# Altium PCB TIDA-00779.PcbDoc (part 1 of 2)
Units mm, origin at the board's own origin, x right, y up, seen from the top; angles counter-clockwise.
Board outline 200 x 145 mm, 2 copper layers (Top Layer, Bottom Layer), stack 1.57 mm thick; 147 components, 60 nets, 299 pads, 545 vias.
Unrouted connection lines stored in the file: 4.
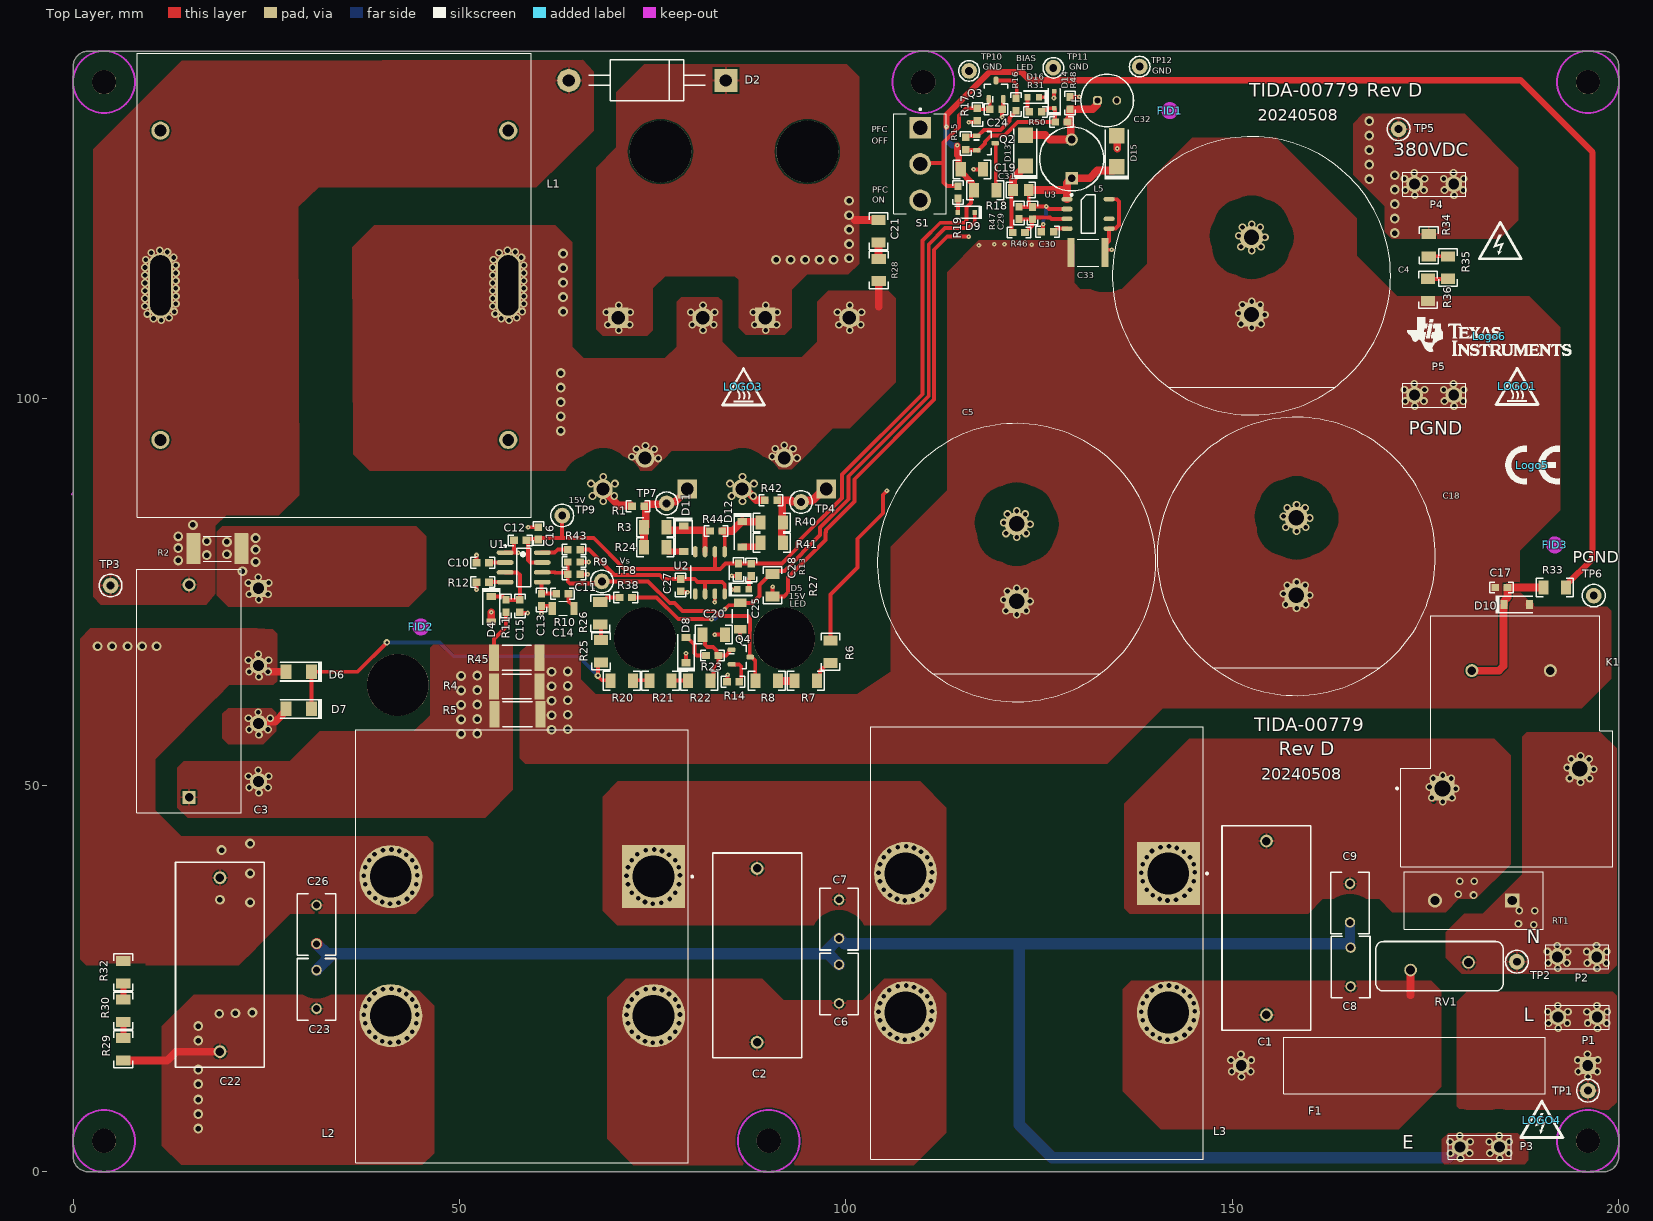
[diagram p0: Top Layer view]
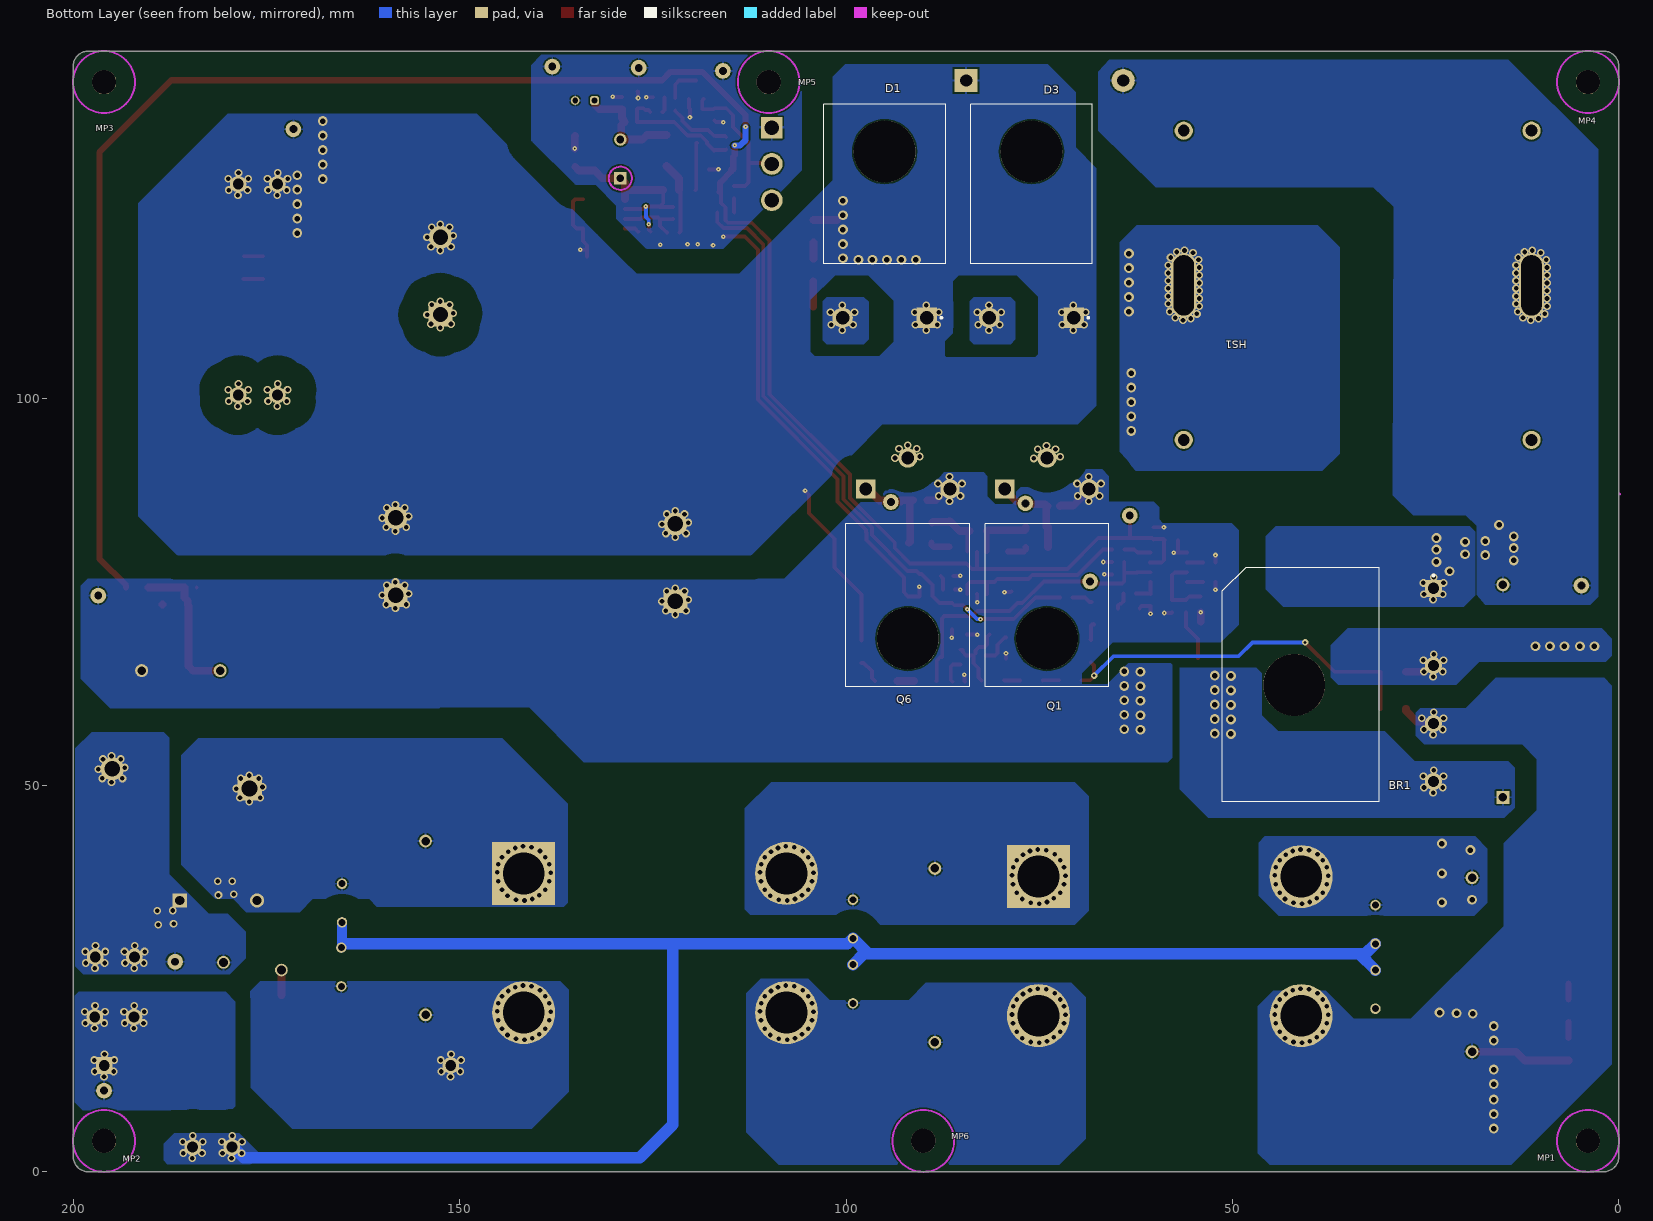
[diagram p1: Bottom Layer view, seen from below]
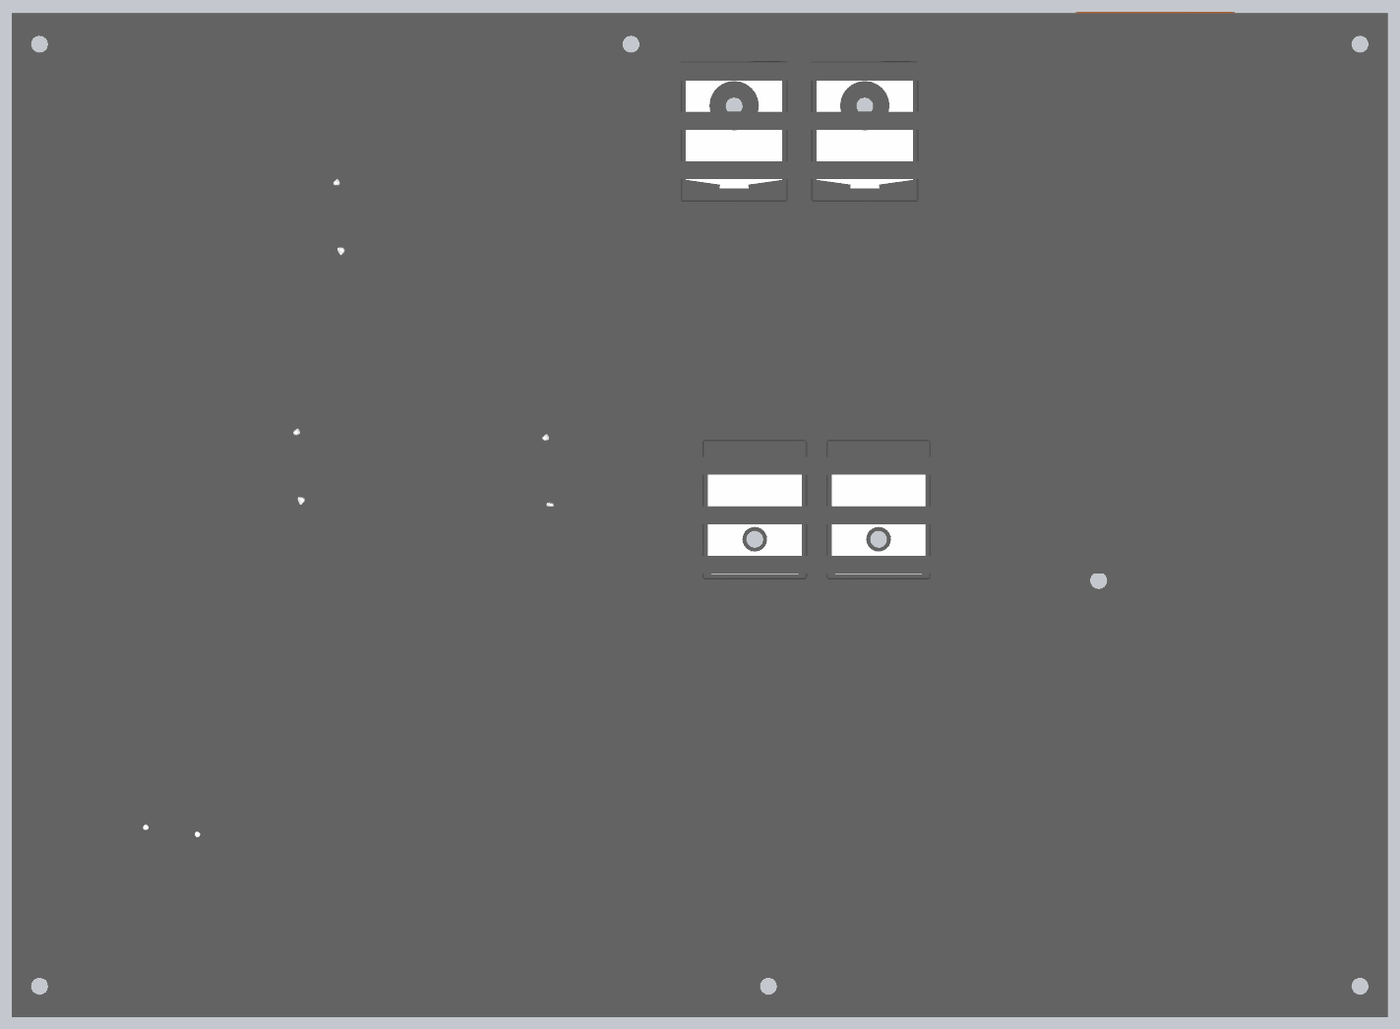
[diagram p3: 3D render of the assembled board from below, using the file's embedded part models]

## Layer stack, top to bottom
Top Solder: solder mask 0.0102, Solder Resist, Dk 3.5
Top Layer: signal copper 0.0356
Dielectric1: core 1.4986, Core-043, Dk 4.3
Bottom Layer: signal copper 0.0356
Bottom Solder: solder mask 0.0102, Solder Resist, Dk 3.5

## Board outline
0,2 0,143 cw(c2,143) 2,145 198,145 cw(c198,143) 200,143 200,2 cw(c198,2) 198,0 2,0 cw(c2,2)

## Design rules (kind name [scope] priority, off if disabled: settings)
AcuteAngle [All] p1: minimum=4.50000000000000E+0001 checktracksonly=FALSE
AssemblyTestPointUsage [All] p1: valid=2
Clearance ACN2EARTH [InNetClass('ACN') vs InNetClass('EARTH')] p1: gap=3 ignorepadtopadclearanceinfootprint=FALSE
Clearance ACN2GND [InNetClass('ACN') vs InNetClass('PGND')] p2: gap=2 ignorepadtopadclearanceinfootprint=FALSE
Clearance ACL2EARTH [InNetClass('ACL') vs InNetClass('EARTH')] p3: gap=3 ignorepadtopadclearanceinfootprint=FALSE
Clearance DCBUS2PGND [InNetClass('DCBUS') vs InNetClass('PGND')] p4: gap=3.2 ignorepadtopadclearanceinfootprint=FALSE
Clearance ACL2ACN [InNetClass('ACL') vs InNetClass('ACN')] p5: gap=2 ignorepadtopadclearanceinfootprint=FALSE
Clearance Clearance_BoardEdge_MountingHoles [OnCopper and InComponentClass('Mounting Holes') vs IsKeepOut] p6: gap=0.3 ignorepadtopadclearanceinfootprint=FALSE except(0: Arc-Hole Track-Hole SMDPad-Hole THPad-Hole Via-Hole Fill-Hole Poly-Hole Region-Hole Text-Hole)
Clearance Clearance_BoardEdge_Poly [OnCopper and InPoly vs IsKeepOut] p7 off: gap=0.25 ignorepadtopadclearanceinfootprint=FALSE except(0: Arc-Hole Track-Hole SMDPad-Hole THPad-Hole Via-Hole Fill-Hole Poly-Hole Region-Hole Text-Hole)
Clearance Clearance_BoardEdge [OnCopper and Not InComponentClass('Logo') and not InComponentClass('FiducialMark') and not InRegion(1000,500,4000,800) and Not IsKeepout vs IsKeepOut] p8 off: gap=1.905 ignorepadtopadclearanceinfootprint=FALSE except(0: Arc-Hole Track-Hole SMDPad-Hole THPad-Hole Via-Hole Fill-Hole Poly-Hole Region-Hole Text-Hole)
Clearance Clearance_Poly [InPolygon] p9: gap=0.2 ignorepadtopadclearanceinfootprint=FALSE
Clearance [All] p10: gap=0.2 ignorepadtopadclearanceinfootprint=FALSE
ComponentClearance ComponentClearance_MountingHoles_FiducialMarks [InComponentClass('Mounting Holes') vs InComponentClass('FiducialMark')] p1 off: gap=1.27 collisioncheckmode=3 verticalgap=0.254 showdistances=FALSE
ComponentClearance ComponentClearance_Shunt [InComponentClass('Header') vs InComponentClass('Shunt')] p2 off: gap=0 collisioncheckmode=3 verticalgap=0 showdistances=FALSE
ComponentClearance ComponentClearance_Logo [InComponentClass('Logo')] p3 off: gap=1.27 collisioncheckmode=3 verticalgap=0.254 showdistances=FALSE
ComponentClearance ComponentClearance_ScrewToNut [(HasFootprint('NY PMS 440 0025 PH')) vs (HasFootprint('Keystone_1902C'))] p4 off: gap=0.127 collisioncheckmode=3 verticalgap=0.254 showdistances=FALSE
ComponentClearance ComponentClearance_MountingHoles [InComponentClass('Mounting Holes')] p5 off: gap=6.35 collisioncheckmode=3 verticalgap=2540 showdistances=FALSE
ComponentClearance ComponentClearance_SmallPassives [HasFootprint('0201*') or HasFootprint('0402*') or HasFootprint('0508') or HasFootprint('0603*') or HasFootprint('0612') or HasFootprint('0805*') or HasFootprint('0815*') or HasFootprint('0830*') or HasFootprint('1206*') or HasFootprint('1210*') or HasFootprint('1808*') or HasFootprint('1812*') or HasFootprint('1825*') or HasFootprint('2010*') or HasFootprint('2220*') or HasFootprint('2225*') or HasFootprint('2512*') or HasFootprint('2728*') or HasFootprint('3518*') vs HasFootprint('0201*') or HasFootprint('0402*') or HasFootprint('0508') or HasFootprint('0603*') or HasFootprint('0612') or HasFootprint('0805*') or HasFootprint('0815*') or HasFootprint('0830*') or HasFootprint('1206*') or HasFootprint('1210*') or HasFootprint('1808*') or HasFootprint('1812*') or HasFootprint('1825*') or HasFootprint('2010*') or HasFootprint('2220*') or HasFootprint('2225*') or HasFootprint('2512*') or HasFootprint('2728*') or HasFootprint('3518*')] p6 off: gap=0.508 collisioncheckmode=3 verticalgap=0.254 showdistances=FALSE
ComponentClearance ComponentClearance_THtoSMT [IsThruComponent vs IsSMTComponent] p7 off: gap=2.54 collisioncheckmode=3 verticalgap=0.762 showdistances=FALSE
ComponentClearance ComponentClearance_THtoTH [IsThruComponent vs IsThruComponent] p8 off: gap=3 collisioncheckmode=3 verticalgap=0.762 showdistances=FALSE
ComponentClearance [All] p9 off: gap=1.016 collisioncheckmode=3 verticalgap=0.254 showdistances=FALSE
DiffPairsRouting [All] p1: maxlimit=2.54 minlimit=0.254 mostfreqgap=0.254 toplayer_minwidth=0.381 toplayer_maxwidth=0.381 toplayer_prefwidth=0.381 bottomlayer_minwidth=0.381 bottomlayer_maxwidth=0.381 bottomlayer_prefwidth=0.381 maxuncoupledlength=25.4
FabricationTestPointUsage TestPointUsage [All] p1: valid=2 allowmultiple=FALSE
FabricationTestpoint Testpoint [All] p1: side=3 testpointundercomponent=TRUE minsize=1.016 maxsize=2.54 preferedsize=1.524 minholesize=0 maxholesize=1.016 preferedholesize=0.813 testpointgrid=0.025 allowsidetop=TRUE allowsidebottom=TRUE usegrid=TRUE gridtolerance=0
FanoutControl Fanout_LCC [IsLCC] p1: bgadir=Out bgaviamode=Centered fanoutstyle=Auto fanoutdirection=Alternating viagrid=0.025 // Fanout_LCC (Default Rule)
FanoutControl Fanout_BGA [IsBGA] p2: bgadir=Out bgaviamode=Centered fanoutstyle=Auto fanoutdirection=Alternating viagrid=0.025 // Fanout_BGA (Default Rule)
FanoutControl Fanout_Default [All] p4: bgadir=Out bgaviamode=Centered fanoutstyle=Auto fanoutdirection=Alternating viagrid=0.025 // Fanout_Default (Default Rule)
FanoutControl Fanout_Small [(CompPinCount < 5)] p5: bgadir=Out bgaviamode=Centered fanoutstyle=Auto fanoutdirection=OutThenIn viagrid=0.025 // Fanout_Small (Default Rule)
HoleSize [All] p1: absolutevalues=TRUE maxlimit=6.375 minlimit=0.2 maxpercent=80.000 minpercent=20.000
MinimumAnnularRing MinimumAnnularRing_ThermalPadVias [IsVia and InAnyComponent] p1: minimumring=0.15
MinimumAnnularRing [All] p2: minimumring=0.2
MinimumSolderMaskSliver MinimumSolderMaskSliver_Logo [InComponentClass('Logo') vs InComponentClass('Logo')] p1: minsoldermaskwidth=0.018
MinimumSolderMaskSliver [All] p2: minsoldermaskwidth=0.1
PlaneClearance [All] p1: clearance=0.2
PlaneConnect [All] p1: planeconnectstyle=Relief reliefexpansion=0.2 reliefentries=4 reliefconductorwidth=0.2 reliefairgap=0.2
PolygonConnect PolygonDirect [InComponent('L2') or InComponent('L3') or InComponent('K1') or InComponent('L1') or InComponent('D1') or InComponent('D3') or InComponent('C4') or InComponent('C5') or InComponent('C18') or InComponent('F1')  or InComponent('RT1') or InComponent('P1') or InComponent('P2') or InComponent('P3') or InComponent('BR1') or InComponent('Q1')  or InComponent('Q6') or InComponent('R4') or InComponent('R5') or InComponent('R45')or InComponent('R2')or InComponent('P4') or InComponent('P5')] p1: connectstyle=Direct reliefconductorwidth=0.2 reliefentries=4 polygonreliefangle="90 Angle" airgapwidth=0.2
PolygonConnect [All] p2: thpad.connectstyle=Relief thpad.reliefconductorwidth=0.3 thpad.reliefentries=4 thpad.polygonreliefangle="90 Angle" thpad.airgapwidth=0.2 smdpad.connectstyle=Direct smdpad.reliefconductorwidth=0.3 smdpad.reliefentries=4 smdpad.polygonreliefangle="90 Angle" smdpad.airgapwidth=0.2 via.connectstyle=Direct via.reliefconductorwidth=0.2 via.reliefentries=4 via.polygonreliefangle="90 Angle" via.airgapwidth=0.2
RoutingVias ThermalPadVias [IsVia and InAnyComponent] p1: holewidth=0.2 width=0.5 viastyle="Through Hole" minholewidth=0.2 minwidth=0.5 maxholewidth=0.33 maxwidth=0.6
RoutingVias [All] p2: holewidth=0.2 width=0.6 viastyle="Through Hole" minholewidth=0.2 minwidth=0.6 maxholewidth=1 maxwidth=4
SilkToSilkClearance SilkToSilkClearance_Pb-FreeLogo [(HasFootprint('Pb-Free_Overlay_Medium') OR HasFootprint('Pb-Free_Overlay_Small')) vs (HasFootprint('Pb-Free_Overlay_Medium') OR HasFootprint('Pb-Free_Overlay_Small'))] p1: silktosilkclearance=0
SilkToSilkClearance [All] p2: silktosilkclearance=0.102
SilkToSolderMaskClearance "Silk to Solder Mask Opening" [IsPad] p1: minsilkscreentomaskgap=0.102 clearancetoexposedcopper=TRUE
SolderMaskExpansion [All] p1: expansion=0.05 istentingtop=FALSE
Width [All] p1: maxlimit=10 minlimit=0.2 preferedwidth=0.254 minimp=50.000000 maximp=50.000000 favimp=50.000000 checkconnectedcopper=TRUE
15 further rules are at their usual default settings.

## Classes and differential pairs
component class Logo: Logo6
net class EARTH: GNDE
net class DCBUS: NetBR1_1 NetC3_2 NetC21_2 NetD1_2 NetR34_1 VDCBUS
net class ACL: NetBR1_3 NetC1_2 NetC2_2 NetF1_1 NetR29_1 NetR30_1
net class ACN: NetBR1_2 NetBR1_3 NetC1_2 NetC2_1 NetC2_2 RLY-N RLY-P
net class PGND: 15V ACSENSE BIAS InrushDelay NetC10_1 NetC13_1 NetC14_2 NetC15_1 NetC17_1 NetC24_1 NetC27_1 NetC32_1 NetD5_1 NetD8_2 NetD9_2 NetD11_1 NetD11_2 NetD12_1 NetD12_2 NetD16_1 NetL1_1 NetL1_2 NetL1_3 NetL1_4 NetQ1_1 NetQ2_1 NetQ2_3 NetQ3_3 NetQ4_2 NetQ6_1 NetR6_1 NetR7_1 NetR12_2 NetR21_1 NetR26_1 NetR35_1 NetR43_1 NetS1_1 NetU2_1 NetU2_8 PGND RTN Vsense
component class FiducialMark: FID1 FID2 FID3

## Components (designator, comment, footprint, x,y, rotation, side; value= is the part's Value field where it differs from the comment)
BR1 "GBJ3510" FP-GBJ3510_HOR_GBJ3510_HOR-MFG 41.15,63 r90 bottom locked
C1 "890334026027CS" WCAP-FTXX_L26W11H20_CS 154.4,31.55 r270 top
C2 "890334026027CS" WCAP-FTXX_L26W11H20_CS 88.5,28 r270 top
C3 "890334027012CS" FP-890334027012CS_RADIAL-MFG 15,62.2 r90 top value=1.2µF
C4 "861141486026" FP-861141486026_RADIAL-MFG 152.464,115.923 r90 top locked value=680µF
C5 "861141486026" FP-861141486026_RADIAL-MFG 122.064,78.823 r90 top value=680µF
C6 "DE2E3KY222MA2BM01F" KY_800x500x1100 99.1,24.3 r270 top value=2200pF
C7 "DE2E3KY222MA2BM01F" KY_800x500x1100 99.1,32.7 r90 top value=2200pF
C8 "DE2E3KY222MA2BM01F" KY_800x500x1100 165.3,26.5 r270 top value=2200pF
C9 "DE2E3KY222MA2BM01F" KY_800x500x1100 165.207,34.774 r90 top value=2200pF
C10 "GRM188R72A332KA01D" 0603 53,78.8 r180 top value=3300pF
C11 "GRM188R71H821KA01D" 0603 64.8,77.3 r0 top value=820pF
C12 "GRT188R61H105ME13D" 0603 57.85,81.7 r180 top value=1uF
C13 "GRM188R71C394KA88D" 0603 60.6,74 r270 top value=0.39uF
C14 "C1206C825M8RAC7800" FP-C1206C825M8RAC7800_1206-MFG 63.4,72.9 r0 top value=8.2µF
C15 "GRM1885C1H272JA01D" 0603 57.8,73.2 r270 top value=2700pF
C16 "GCM188R71H104KA57D" 0603 60.2,82.6 r90 top value=0.1uF
C17 "GRT188R61H105ME13D" 0603 184.8,75.6 r180 top value=1uF
C18 "861141486026" FP-861141486026_RADIAL-MFG 158.264,79.623 r90 top locked value=680µF
C19 "GRM319R6YA106KA12D" 1206 116.3,129.7 r0 top value=10uF
C20 "GRM319R6YA106KA12D" 1206 82.9,69.5 r0 top value=10uF
C21 "GRM31A7U3A221JW31D" 1206 104.2,121.7 r270 top value=220pF
C22 "890334026027CS" WCAP-FTXX_L26W11H20_CS 19,26.8 r270 top
C23 "DE2E3KY222MA2BM01F" KY_800x500x1100 31.5,23.6 r270 top value=2200pF
C24 "GCM188R71H104KA57D" 0603 119.4,137.475 r0 top value=0.1uF
C25 "C3216X5R1V226M160AC" 1206_180 86.3,71.9 r270 top value=22uF
C26 "DE2E3KY222MA2BM01F" KY_800x500x1100 31.5,32 r90 top value=2200pF
C27 "GRM1885C1H221JA01D" 0603 78.6,75.9 r270 top value=220pF
C28 "GRT188R61H105ME13D" 0603 86.1,77.9 r90 top value=1uF
C29 "GRM1885C1H200JA01D" 0603 124.123,124.036 r90 top value=20pF
C30 "GCM188R71H104KA57D" 0603 126.064,121.623 r180 top value=0.1uF
C31 "GRM219R71H334KA88D" 0805_HV 122.623,127.036 r0 top value=0.33uF
C32 "35ZLJ100M6.3X11" Rubycon_630x1100 133.79,138.609 r0 top value=100uF
C33 "885342211006" FP-885342211006_1812-MFG 131.323,118.936 r0 top value=100nF
D1 "BYC30W-600PQ" FP-BYC30W-600PQ_HOR_TO-247-2-MFG 95,127.8 r180 bottom locked
D2 "1N5406" DO-201AD 74.3,141.2 r180 top value=600V
D3 "BYC30W-600PQ" FP-BYC30W-600PQ_HOR_TO-247-2-MFG 76,127.8 r180 bottom locked
D4 "BAT54T1G" SOD-123 54.1,72.8 r270 top value=30V
D5 "LTST-C193KGKT-5A" LTST-C193_Green 86.677,75.364 r180 top value=Green
D6 "CGRM4007-G" MINI-SMA 29.2,64.7 r180 top value=1000V
D7 "CGRM4007-G" MINI-SMA 29.2,59.9 r180 top value=1000V
D8 "BAT54T1G" SOD-123 79.3,67.5 r90 top value=30V
D9 "MMSZ5248BS-7-F" SOD-323 115.567,124.125 r180 top value=18V
D10 "BAT54T1G" SOD-123 186.8,73.4 r0 top value=30V
D11 "1N4148W-7-F" SOD-123 79,81.9 r270 top value=100V
D12 "1N4148W-7-F" SOD-123 86.6,82.5 r270 top value=100V
D13 "US1M-13-F" SMA 123.223,132.136 r90 top value=1000V
D14 "MMSZ5248BS-7-F" SOD-323 126.959,138.7 r90 top value=18V
D15 "US1M-13-F" SMA 135.023,132.036 r90 top value=1000V
D16 "LTST-C193KRKT-5A" LTST-C193_Red 124.223,139.036 r0 top value=Red
F1 "0525025.MXEP" FP-0525025.MXEP_AXIAL-MFG 173.551,13.758 r180 top
FID1 "Fiducial" Fiducial10-20 141.9,137.3 r0 top
FID2 "Fiducial" Fiducial10-20 45,70.5 r0 top
FID3 "Fiducial" Fiducial10-20 191.7,81.1 r0 top
HS1 "TIDA-00779 Heatsink" 0-MFG 100,72.5 r270 bottom
K1 "T9AS1D12-12" FP-T9AS1D12-12_PTH_RELAY_27MM43_32MM51-MFG 185.499,55.7 r180 top
L1 "30A_170uH" FP-30A_170uH_PTH_IND_60MM0_51MM0-MFG 33.8,114.7 r90 top value=170uH
L2 "30A_2.5mH" FP-30A_2.5mH_PTH_CMC_56MM0_42MM0-MFG 58.1,29.2 r270 top
L3 "30A_2.5mH" FP-30A_2.5mH_PTH_CMC_56MM0_42MM0-MFG 124.7,29.6 r270 top
L5 "768772182" WE-TI_8095 129.197,131.05 r90 top value=1.8mH
LOGO1 "CAUTION HOT SURFACE" IEC_HotSurface_Small 186.823,101.636 r0 top
LOGO3 "CAUTION HOT SURFACE" IEC_HotSurface_Small 86.736,101.577 r0 top
LOGO4 "DANGER HIGH VOLTAGE" IEC_HighVoltage_Small 190.036,6.677 r0 top
Logo5 "CE Mark" CE_Mark_5mm 188.823,91.436 r0 top
Logo6 "Texas Instruments" TI_Stacked_Overlay_Small 183.236,108.077 r0 top
MP1 "970130365" FP-970130365_SPCAER_M3-MFG 4,4 r180 bottom
MP2 "970130365" FP-970130365_SPCAER_M3-MFG 196,4 r180 bottom
MP3 "970130365" FP-970130365_SPCAER_M3-MFG 196,141 r180 bottom
MP4 "970130365" FP-970130365_SPCAER_M3-MFG 4,141 r180 bottom
MP5 "970130365" FP-970130365_SPCAER_M3-MFG 110,141 r180 bottom
MP6 "970130365" FP-970130365_SPCAER_M3-MFG 90,4 r180 bottom
P1 "63824-1" FP-63824-1_CONN_7MM92_3MM11-MFG 194.651,20.025 r0 top
P2 "63824-1" FP-63824-1_CONN_7MM92_3MM11-MFG 194.6,27.8 r180 top
P3 "63824-1" FP-63824-1_CONN_7MM92_3MM11-MFG 182,3.2 r0 top
P4 "63824-1" FP-63824-1_CONN_7MM92_3MM11-MFG 176.1,127.8 r0 top
P5 "63824-1" FP-63824-1_CONN_7MM92_3MM11-MFG 176.1,100.5 r0 top
Q1 "IPW60R099CPFKSA1" FP-IPW60R099CPFKSA1_HOR_TO247-MFG 74,73.305 r180 bottom locked
Q2 "MMBT3906-7-F" SOT-23 118.1,133.1 r0 top value="40 V"
Q3 "2V7002KT1G" SOT-23 119.4,140 r90 top value=60V
Q4 "MMBT3904-7-F" SOT-23 86.4,66.6 r0 top value="40 V"
Q6 "IPW60R099CPFKSA1" FP-IPW60R099CPFKSA1_HOR_TO247-MFG 92,73.305 r180 bottom locked
R1 "RC0603FR-0710KL" 0603 73.1,86.1 r0 top value=10.0k
R2 "RC2512FK-070RL" FP-RC2512FK-070RL_2512-MFG 18.664,80.623 r180 top value=0
R3 "RC1206FR-0722RL" 1206 75.3,83.4 r180 top value=22.0
R4 "ERJ-M1WSF10MU" 2512 57.4,62.8 r180 top value=0.01
R5 "ERJ-M1WSF10MU" 2512 57.5,59.2 r180 top value=0.01
R6 "RC1206FR-07332KL" 1206 98,67.3 r90 top value=332k
R7 "RC1206FR-07332KL" 1206 94.8,63.525 r0 top value=332k
R8 "RC1206FR-07332KL" 1206 89.75,63.525 r0 top value=332k
R9 "RC0603FR-0718KL" 0603 64.8,78.9 r180 top value=18.0k
R10 "RC0603FR-0710KL" 0603 63.3,74.8 r180 top value=10.0k
R11 "RC0603FR-07220RL" 0603 56,73.2 r270 top value=220
R12 "RC0603FR-0747KL" 0603 53,76.3 r0 top value=47.0k
R13 "RC0603FR-0710KL" 0603 87.736,77.877 r270 top value=10.0k
R14 "RC0603FR-0716K2L" 0603 85.4,63.4 r0 top value=16.2k
R15 "RC0603FR-0710KL" 0603 115.5,133.05 r90 top value=10.0k
R16 "RC0603FR-071KL" 0603 122,138.1 r90 top value=1.00k
R17 "RC0603FR-0747KL" 0603 117,136.8 r90 top value=47.0k
R18 "RC1206FR-071RL" 1206 118,127 r180 top value=1.00
R19 "RC0603FR-0710KL" 0603 114.5,126.725 r270 top value=10.0k
R20 "RC1206FR-07332KL" 1206 71,63.544 r180 top value=332k
R21 "RC1206FR-07332KL" 1206 76.002,63.544 r180 top value=332k
R22 "RC1206FR-07332KL" 1206 81,63.544 r180 top value=332k
R23 "RC0603FR-0710KL" 0603 82.7,66.8 r0 top value=10.0k
R24 "RC1206FR-074R7L" 1206 75.3,80.8 r180 top value=4.70
R25 "RC1206FR-07332KL" 1206 68.3,67.35 r270 top value=332k
R26 "RC1206FR-07332KL" 1206 68.2,72.25 r270 top value=332k
R27 "RC1206FR-07332KL" 1206 90.5,75.9 r90 top value=332k
R28 "RC1206FR-0722RL" 1206 104.236,116.677 r270 top value=22.0
R29 "RC1206FR-07100KL" 1206 6.5,15.85 r270 top value=100k
R30 "RC1206FR-07100KL" 1206 6.5,20.85 r270 top value=100k
R31 "RC0603FR-0710KL" 0603 124.523,137.136 r0 top value=10.0k
R32 "RC1206FR-07100KL" 1206 6.5,25.8 r270 top value=100k
R33 "RC1206FR-0722RL" 1206 191.7,75.6 r180 top value=22.0
R34 "RC1206FR-07100KL" 1206 175.4,119.9 r90 top value=100k
R35 "RC1206FR-07100KL" 1206 177.9,117 r90 top value=100k
R36 "RC1206FR-07100KL" 1206 175.3,114.1 r90 top value=100k
R38 "RC0603FR-0747KL" 0603 71.5,74.3 r180 top value=47.0k
R40 "RC1206FR-0722RL" 1206 90.4,84 r0 top value=22.0
R41 "RC1206FR-074R7L" 1206 90.4,81.4 r0 top value=4.70
R42 "RC0603FR-0710KL" 0603 90.3,86.9 r0 top value=10.0k
R43 "RT0603DRE07100RL" 0603 64.8,80.5 r0 top value=100
R44 "RC0603JR-070RL" 0603 83.2,82.9 r0 top value=0
R45 "ERJ-M1WSF10MU" 2512 57.4,66.5 r180 top value=0.01
R46 "RC0603FR-07133KL" 0603 122.364,121.523 r180 top value=133k
R47 "RC0603FR-0710KL" 0603 122.377,124.064 r270 top value=10.0k
R48 "RC0603FR-0721KL" 0603 128.977,138.264 r270 top value=21.0k
R50 "RC0603JR-070RL" 0603 127.864,135.823 r180 top value=0
RT1 "PPL16500NA2B7Y" FP-PPL16500NA2B7Y_RADIAL-MFG 181.2,35.1 r180 top value=50Ω
RV1 "MOV-14D471K" Bourns_MOV-14D621K 176.8,26.6 r180 top
S1 "472123010111" FP-472123010111_PTH3-MFG 109.6,130.4 r90 top
TP1 "5000" Keystone5000 196,10.5 r0 top value=Red
TP2 "5000" Keystone5000 186.8,27.187 r0 top value=Red
TP3 "5000" Keystone5000 4.85,75.85 r0 top value=Red
TP4 "5000" Keystone5000 94.187,86.662 r0 top value=Red
TP5 "5000" Keystone5000 171.5,134.9 r0 top value=Red
TP6 "5001" Keystone5001 196.75,74.55 r0 top value=Black
TP7 "5000" Keystone5000 76.783,86.485 r0 top value=Red
TP8 "5000" Keystone5000 68.417,76.385 r0 top value=Red
TP9 "5000" Keystone5000 63.281,84.906 r0 top value=Red
TP10 "5001" Keystone5001 115.923,142.436 r90 top
TP11 "5001" Keystone5001 126.823,142.836 r90 top
TP12 "5001" Keystone5001 138,143 r90 top
U1 "UCC28180D" D0008A_N#1 58.3,78.2 r0 top
U2 "UCC27524DR" D0008A_N#2 82.4,77.5 r90 top
U3 "UCC28881DR" D0007A_N 131.323,123.936 r0 top
? "DANGER HIGH VOLTAGE" IEC_HighVoltage_Small 184.636,120.377 r0 top

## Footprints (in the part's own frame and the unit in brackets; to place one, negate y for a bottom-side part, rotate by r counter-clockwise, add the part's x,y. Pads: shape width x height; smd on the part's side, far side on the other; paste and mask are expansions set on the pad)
0-MFG [mm]
  body extent -73,-100 73,100, height 22
0603 [mm] "0603 from SM-752 data"
  rect 1x0.95 smd: 1(-0.8,0) 2(0.8,0)
  silkscreen extent -1.52,-0.69 1.52,0.69, body extent -0.87,-0.47 0.87,0.47, height 1
0805_HV [mil] "0805 with 30mil clearance between pads"
  rect 50x63 smd: 1(-40,0) 2(40,0)
  silkscreen extent -74,-40 74,40, body extent -43,-29 43,29, height 57
1206 [mm] "1206 from SM-752 data"
  rect 1.3x1.85 smd: 1(-1.45,0) 2(1.45,0)
  silkscreen extent -2.4,-1.21 2.4,1.21, body extent -1.7,-0.9 1.7,0.9, height 1.35
1206_180 [mm] "1206_180"
  rect 1.1x1.6 smd: 1(-1.7,0) 2(1.7,0)
  silkscreen extent -0.9,-1 0.9,1, body extent -1.75,-0.95 1.75,0.95, height 1.8
2512 [mm] "Chip Resistor, Body 6.3x3.2mm, IPC Medium Density"
  rect 1.3x3.4 smd: 1(-2.95,0) 2(2.95,0)
  silkscreen extent -1.9,-1.6 1.9,1.6, body extent -3.22,-1.67 3.22,1.67, height 0.71
Bourns_MOV-14D621K [mm] "TH, 2-Leads, Dia 16.5mm"
  round 1.65 hole 1.15: 1(-3.75,-0.5) 2(3.75,0.5)
  silkscreen extent -8.25,-3.2 8.25,3.2, body extent -8.25,-3.2 8.25,3.2, height 21.97
CE_Mark_5mm [mm] "Minimum text height for CE Mark"
  silkscreen extent -3.5,-2.5 3.5,2.5
D0007A_N [mm] "SOIC, 7-Leads, Body 4.9x3.9mm, Pitch 1.27mm, IPC Medium Density"
  oval 1.45x0.6 smd: 1(-2.725,1.905) 2(-2.725,0.635) 3(-2.725,-0.635) 4(-2.725,-1.905) 5(2.725,-1.905) 6(2.725,-0.635) 8(2.725,1.905)
  silkscreen extent -0.9,-2.5 0.9,2.5, body extent -3.01,-2.45 3.01,2.45, height 1.75
D0008A_N#1 [mm] "SOIC, 8-Leads, Body 4.9x3.9mm, Pitch 1.27mm, IPC Medium Density"
  oval 2.2x0.6 smd: 1(-2.4,1.905) 2(-2.4,0.635) 3(-2.4,-0.635) 4(-2.4,-1.905) 5(2.4,-1.905) 6(2.4,-0.635) 7(2.4,0.635) 8(2.4,1.905)
  silkscreen extent -2.52,-2.5 0.9,2.88, body extent -2,-2.5 2,2.5, height 1.75
D0008A_N#2 [mm] "SOIC, 8-Leads, Body 4.9x3.9mm, Pitch 1.27mm, IPC Medium Density"
  oval 1.45x0.6 smd: 1(-2.725,1.905) 2(-2.725,0.635) 3(-2.725,-0.635) 4(-2.725,-1.905) 5(2.725,-1.905) 6(2.725,-0.635) 7(2.725,0.635) 8(2.725,1.905)
  silkscreen extent -3.3,-2.5 0.9,2.5, body extent -3,-2.45 3,2.45, height 1.63
DO-201AD [mm] "Vishay dimensions"
  rect 3x3 hole 1.6: 1(-10.16,0)
  round 3 hole 1.6: 2(10.16,0)
  silkscreen extent -7.47,-2.7 7.57,2.61, body extent -10.82,-2.74 10.82,2.61, height 5.33
Fiducial10-20 [mm]
  round 1 smd mask+0.5: 1(0,0)
  Top Layer keep-out circle w1.178: c0,0 r0.5
FP-30A_2.5mH_PTH_CMC_56MM0_42MM0-MFG [mm]
  rrect1% 8.15x8.15 hole 5.4 paste-2539.97 mask+0: 1(-9,17)
  round 8.15 hole 5.4 paste-2539.97 mask+0: 2(-9,-17) 3(9,-17) 4(9,17)
  silkscreen extent -28,-21.5 28,22.13, body extent -28.1,-21.6 28.1,21.6, height 0.25
FP-30A_170uH_PTH_IND_60MM0_51MM0-MFG [mm]
  round 2.35 hole 1.55 paste-2539.97 mask+0: 1(-20,22.5) 2(20,22.5) 3(-20,-22.5) 4(20,-22.5)
  rrect100% 8.4x3.25 hole 2.65 slot 7.8 at 0 deg paste-2539.97 mask+0: N(0,-22.5) S(0,22.5)
  silkscreen extent -30,-25.5 30,25.5, body extent -30.1,-25.6 30.1,25.6, height 0.25
FP-63824-1_CONN_7MM92_3MM11-MFG [mm]
  round 2.15 hole 1.4 paste-2539.97 mask+0: 1(-2.54,0) 1(2.54,0)
  silkscreen extent -4.09,-1.56 4.09,1.56, body extent -3.96,-1.54 3.96,1.54, height 10.88
FP-0525025.MXEP_AXIAL-MFG [mm]
  rrect5% 2.15x2.15 hole 1.4 paste-2539.97 mask+0: 1(-22.42,0)
  round 2.15 hole 1.4 paste-2539.97 mask+0: 2(22.42,0)
  silkscreen extent -16.92,-3.64 16.92,3.64, body extent -23.59,-3.74 23.59,3.74, height 0.25
FP-970130365_SPCAER_M3-MFG [mm]
  round 3.15 hole 3.15 unplated paste-2539.97 mask+0: ""(0,0)
  body extent -3.46,-3 3.46,3, height 13.1
FP-472123010111_PTH3-MFG [mm]
  rrect4% 2.8x2.8 hole 1.85 paste-2539.97 mask+0: 1(4.7,0)
  round 2.8 hole 1.85 paste-2539.97 mask+0: 2(0,0) 3(-4.7,0)
  silkscreen extent -6.48,-3.4 7.2,3.4, body extent -6.58,-3.5 6.58,3.5, height 0.25
FP-861141486026_RADIAL-MFG [mm]
  rrect3% 3.05x3.05 hole 2 paste-2539.97 mask+0: 1(-5,0)
  round 3.05 hole 2 paste-2539.97 mask+0: 2(5,0)
  silkscreen extent -18,-18 18,18, body extent -18.1,-18.1 18.1,18.1, height 0.25
FP-885342211006_1812-MFG [mm]
  rrect11% 0.9x3.8 smd paste+0 mask+0: 1(-2.2,0) 2(2.2,0)
  silkscreen extent -1.38,-1.75 1.38,1.75, body extent -2.75,-2 2.75,2, height 0.25
FP-890334027012CS_RADIAL-MFG [mm]
  rrect6% 1.7x1.7 hole 1.1 paste-2539.97 mask+0: 1(-13.75,0)
  round 1.7 hole 1.1 paste-2539.97 mask+0: 2(13.75,0)
  silkscreen extent -15.75,-6.75 15.75,6.75, body extent -15.85,-6.85 15.85,6.85, height 0.25
FP-BYC30W-600PQ_HOR_TO-247-2-MFG [mm]
  rrect4% 2.65x2.65 hole 1.75 paste-2539.97 mask+0: 1(5.45,-17.3)
  round 2.65 hole 1.75 paste-2539.97 mask+0: 2(-5.45,-17.3)
  round 8 hole 8 unplated paste-2539.97 mask+0: ""(0,4.2)
  silkscreen extent -7.88,-17.42 7.88,10.3, body extent -7.8,-17.55 7.8,10.73, height 5.2
FP-C1206C825M8RAC7800_1206-MFG [mm]
  rrect11% 0.95x1.7 smd paste+0 mask+0: 1(-1.4,0) 2(1.4,0)
  silkscreen extent -0.55,-0.9 0.55,0.9, body extent -2,-1 2,1, height 0.25
FP-GBJ3510_HOR_GBJ3510_HOR-MFG [mm]
  rrect5% 2.2x2.2 hole 1.45 paste-2539.97 mask+0: 1(12.5,-17.15)
  round 2.2 hole 1.45 paste-2539.97 mask+0: 2(2.5,-17.15) 3(-5,-17.15) 4(-12.5,-17.15)
  round 8 hole 8 unplated paste-2539.97 mask+0: ""(0,0.85)
  silkscreen extent -15.15,-17.27 15.15,10.15, body extent -15,-17.45 15,10.15, height 4.8
FP-IPW60R099CPFKSA1_HOR_TO247-MFG [mm]
  rrect4% 2.5x2.5 hole 1.65 paste-2539.97 mask+0: 1(-5.45,15.038)
  round 2.5 hole 1.65 paste-2539.97 mask+0: 2(0,19.038) 3(5.45,15.038)
  round 8 hole 8 unplated paste-2539.97 mask+0: ""(0,-4.305)
  silkscreen extent -8.01,-10.54 8.01,10.54, body extent -7.93,-10.47 7.93,19.41, height 5.16
FP-PPL16500NA2B7Y_RADIAL-MFG [mm]
  rrect5% 1.85x1.85 hole 1.2 paste-1000 mask+0: 1(-5,0)
  round 1.85 hole 1.2 paste-1000 mask+0: 2(5,0)
  silkscreen extent -9,-3.75 9,3.75, body extent -9.1,-3.85 9.1,3.85, height 0.25
FP-RC2512FK-070RL_2512-MFG [mm]
  rrect6% 1.8x4 smd paste+0 mask+0: 1(-3.1,0) 2(3.1,0)
  silkscreen extent -1.83,-1.63 1.83,1.63, body extent -4.1,-2.1 4.1,2.1, height 0.25
FP-T9AS1D12-12_PTH_RELAY_27MM43_32MM51-MFG [mm]
  rrect3% 3.16x3.16 hole 2.06 paste-2539.97 mask+0: 1(8.335,6.095)
  round 3.03 hole 1.98 paste-2539.97 mask+0: 2(-9.445,3.555)
  round 1.69 hole 1.09 paste-2539.97 mask+0: 3(4.525,-9.145) 4(-5.635,-9.145)
  silkscreen extent -13.71,-16.25 14.31,16.25, body extent -13.81,-16.35 13.81,16.35, height 0.25
IEC_HighVoltage_Small [mm]
  silkscreen extent -2.72,-2.24 2.72,2.47
IEC_HotSurface_Small [mm]
  silkscreen extent -2.72,-2.36 2.72,2.35
Keystone5000 [mil] "For Keystone 500x miniature loop terminals"
  round 80 hole 40: 1(0,0)
  silkscreen extent -58,-58 58,58, body extent -49,-49 49,49, height 182
Keystone5001 [mil] "For Keystone 500x miniature loop terminals"
  round 80 hole 40: 1(0,0)
  silkscreen extent -58,-58 58,58, body extent -49,-49 49,49, height 182
KY_800x500x1100 [mm] "TH, 2- Leads, Body 8x5mm, Pin Spacing 5mm"
  round 1.35 hole 0.9: 1(-2.5,0) 2(2.5,0)
  silkscreen extent -4,-2.5 4,2.5, body extent -4,-2.5 4,2.5, height 12
LTST-C193_Green [mm] "SMD, 2-Leads, Body1.6x0.8mm"
  rect 0.8x0.8 smd: 1(-0.75,0) 2(0.75,0)
  silkscreen extent -1.2,-0.9 1.85,0.9, body extent -0.85,-0.45 0.85,0.45, height 0.45
LTST-C193_Red [mm] "SMD, 2-Leads, Body1.6x0.8mm"
  rect 0.8x0.8 smd: 1(-0.75,0) 2(0.75,0)
  silkscreen extent -1.2,-0.9 1.85,0.9, body extent -0.85,-0.45 0.85,0.45, height 0.45
MINI-SMA [mm] "COMCHIP"
  rect 1.4x1.9 smd: 1(-1.65,0) 2(1.65,0)
  silkscreen extent -3,-1.3 2.4,1.3, body extent -1.95,-0.9 1.95,0.9, height 1.7
Rubycon_630x1100 [mm] "TH, 2-Leads, Dia 6.3mm, Lead Spacing 2.5mm"
  rrect50% 1.125x1.125 hole 0.75: 1(-1.25,0)
  round 1.125 hole 0.75: 2(1.25,0)
  silkscreen extent -3.4,-3.4 3.41,3.4, body extent -3.4,-3.4 3.41,3.4, height 12.51
SMA [mm] "Molded Diode, 2-Leads, Body 4.3x2.6mm, IPC Medium Density, based on OnSemi component dimensions and land pattern"
  rect 2x2 smd: 1(-2,0) 2(2,0)
  silkscreen extent -3.66,-1.57 2.79,1.57, body extent -2.6,-1.3 2.6,1.3, height 2.42
SOD-123 [mm] "On Semi recommended land pattern"
  rect 0.915x1.22 smd: 1(-1.637,0) 2(1.637,0)
  silkscreen extent -2.74,-1.17 2.03,1.17, body extent -1.93,-0.9 1.93,0.9, height 1.35
SOD-323 [mm] "NXP recommended land pattern"
  rect 0.6x0.6 smd paste-0.05: 1(-1.1,0) 2(1.1,0)
  silkscreen extent -2.06,-0.86 1.53,0.86, body extent -1.3,-0.67 1.3,0.68, height 1.1
SOT-23 [mm] "SOT23, 3-Leads, Body 2.9x1.3mm, Pitch 0.95mm, Lead Span 2.5mm, IPC Medium Density"
  rrect50% 1x0.6 smd: 1(-1.2,0.95) 2(-1.2,-0.95) 3(1.2,0)
  silkscreen extent -1.62,-1.5 0.7,1.5, body extent -1.16,-1.45 1.21,1.45, height 1
TI_Stacked_Overlay_Small [mm]
  silkscreen extent -10.63,-2.49 10.63,2.49
WCAP-FTXX_L26W11H20_CS [mm] "Film Capacitors, 26x11x20mm"
  round 1.65 hole 1.1: 1(-11.25,0) 2(11.25,0)
  silkscreen extent -13.25,-5.75 13.25,5.75, body extent -13,-5.5 13,5.5, height 20.05
WE-TI_8095 [mm] "Wurth WE-TI 8095"
  rect 1.6x1.6 hole 1: 1(-2.5,0)
  round 1.6 hole 1: 2(2.5,0)
  silkscreen extent -4.79,-4.15 4.15,4.15, body extent -4.12,-4.14 4.15,4.14, height 10

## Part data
BR1: library part CMP-0121868-2, "Bridge Rectifier Single Phase Standard 1 kV Through Hole GBJ", Digikey Part Number=1655-GBJ3510-ND, Forward Current=35A, Manufacturer="SMC Diode Solutions", Max Surge Forward Current=320A, Operating Temperature Range="-55°C to +150°C", Part Number=GBJ3510_HOR, Peak Reverse Current=5uA, ValueDisplayed=75pF
C1 C2 C22: library part CMP-0112728-1, "WCAP-FTXX Film Capacitor, THT, L26 x W11 x H20mm, 1µF, 310V", Capacitance Tolerance=+/-10%, Insulation Resistance="10000Ohm x F", Manufacturer="Wurth Elektronik", Operating Temperature Max=105°C, Operating Temperature Min=-40°C, Rate of Voltage Rise=170V/us, Rated Voltage (AC)=310V
C3: library part CMP-0090546-1, "1.2µF Film Capacitor 310V  Polypropylene (PP), Metallized Radial", Digikey Part Number=732-5766-ND, Manufacturer="Wurth Electronics", Mouser Part Number=710-890334027012CS, Operating Temperature Range="-40°C to +105°C", Tolerance_%=10%, ValueDisplayed=1.2uF
C4 C5 C18: library part CMP-0035874-1, "680 µF 450 V Aluminum Electrolytic Capacitors Radial, Can - Snap-In 3000 Hrs @ 105°C", Digikey Part Number=732-6298-ND, Leakage Current=1659.52uA, Manufacturer="Wurth Eectronics", Mouser Part Number=710-861141486026, Operating Temperature Range="-25°C to +105°C", Tolerance_%=20%, ValueDisplayed=680uF
C6 C7 C8 C9 C23 C26: library part CMP-0067532-1, "CAP, CERM, 2200 pF, X1 250 VAC/Y2 250 VAC, +/- 20%, E, 8x5mm", Cap_Case=8x5x11mm, Manufacturer=MuRata, Supplier Part Number 1=490-9468-ND, TempCo=E, Tolerance_%=20%, Value1=Unknown, Value2=V, ValueDisplayed=2200pF
C10: library part CMP-0007479-4, "CAP, CERM, 3300 pF, 100 V, +/- 10%, X7R, 0603", Cap_Case=0603, Manufacturer=MuRata, Supplier Part Number 1=490-1481-1-ND, TempCo=X7R, Tolerance_%=10%, Value1=Unknown, Value2=100V, ValueDisplayed=3300pF
C11: library part CMP-0007464-4, "CAP, CERM, 820 pF, 50 V, +/- 10%, X7R, 0603", Cap_Case=0603, Manufacturer=MuRata, Supplier Part Number 1=490-1493-1-ND, TempCo=X7R, Tolerance_%=10%, Value1=Unknown, Value2=50V, ValueDisplayed=820pF
C12 C17 C28: library part CMP-0081784-1, "CAP, CERM, 1 µF, 50 V,+/- 20%, X5R, AEC-Q200 Grade 3, 0603", Cap_Case=0603, Manufacturer=MuRata, Supplier Part Number 1=490-12331-1-ND, TempCo=X5R, Tolerance_%=20%, Value2=50V, ValueDisplayed=1µF
C13: library part CMP-0007395-4, "CAP, CERM, 0.39 uF, 16 V, +/- 10%, X7R, 0603", Cap_Case=0603, Manufacturer=MuRata, Supplier Part Number 1=GRM188R71C394KA88D-ND, TempCo=X7R, Tolerance_%=10%, Value1=Unknown, Value2=16V, ValueDisplayed=0.39uF
C14: library part CMP-0122046-1, "Cap Ceramic 8.2uF 10V X7R 20% SMD 1206 125°C Plastic T/R", Digikey Part Number=399-C1206C825M8RAC7800TR-ND, Manufacturer=KEMET, Mouser Part Number=80-C1206C825M8R, Operating Temperature Range="-55°C to +125°C", TempCo=15%, Temperature Characteristic=X7R, Tolerance_%=20%, ValueDisplayed=8.2uF
C15: library part CMP-0007204-4, "CAP, CERM, 2700 pF, 50 V, +/- 5%, C0G/NP0, 0603", Cap_Case=0603, Manufacturer=MuRata, Supplier Part Number 1=490-3283-1-ND, TempCo=C0G/NP0, Tolerance_%=5%, Value1=Unknown, Value2=50V, ValueDisplayed=2700pF
C16 C24 C30: library part CMP-0007144-4, "CAP, CERM, 0.1 uF, 50 V, +/- 10%, X7R, 0603", Cap_Case=0603, Manufacturer=MuRata, Supplier Part Number 1=490-4779-1-ND, TempCo=X7R, Tolerance_%=10%, Value1="0.02 ohm", Value2=50V, ValueDisplayed=0.1uF
C19 C20: library part CMP-0081637-1, "CAP, CERM, 10 µF, 35 V,+/- 10%, X5R, 1206", Cap_Case=1206, Manufacturer=MuRata, Supplier Part Number 1=490-9964-1-ND, TempCo=X5R, Tolerance_%=10%, Value1="0.001 ohm", Value2=35V, ValueDisplayed=10µF
C21: library part CMP-0008899-2, "CAP, CERM, 220 pF, 1000 V, +/- 5%, U2J, 1206", Cap_Case=1206, Manufacturer=MuRata, Supplier Part Number 1=490-4303-1-ND, TempCo=U2J, Tolerance_%=5%, Value1=Unknown, Value2=1000V, ValueDisplayed=220pF
C25: library part CMP-0008667-2, "CAP, CERM, 22 uF, 35 V, +/- 20%, X5R, 1206", Cap_Case=1206_180, Manufacturer=TDK, Supplier Part Number 1=445-8045-1-ND, TempCo=X5R, Tolerance_%=20%, Value1="0.002398 ohm", Value2=35V, ValueDisplayed=22uF
C27: library part CMP-0007197-4, "CAP, CERM, 220 pF, 50 V, +/- 5%, C0G/NP0, 0603", Cap_Case=0603, Manufacturer=MuRata, Supplier Part Number 1=490-1435-1-ND, TempCo=C0G/NP0, Tolerance_%=5%, Value1=Unknown, Value2=50V, ValueDisplayed=220pF
C29: library part CMP-0007193-4, "CAP, CERM, 20 pF, 50 V, +/- 5%, C0G/NP0, 0603", Cap_Case=0603, Manufacturer=MuRata, Supplier Part Number 1=490-1410-1-ND, TempCo=C0G/NP0, Tolerance_%=5%, Value1=Unknown, Value2=50V, ValueDisplayed=20pF
C31: library part CMP-0008227-2, "CAP, CERM, 0.33 uF, 50 V, +/- 10%, X7R, 0805", Cap_Case=0805, Manufacturer=MuRata, Supplier Part Number 1=490-3327-1-ND, TempCo=X7R, Tolerance_%=10%, Value1=Unknown, Value2=50V, ValueDisplayed=0.33uF
C32: library part CMP-0080807-1, "CAP, AL, 100 µF, 35 V, +/- 20%, TH", Cap_Case=6.3x11, Manufacturer=Rubycon, Supplier Part Number 1=1189-2268-ND, Tolerance_%=20%, Value2=35V, ValueDisplayed=100µF
C33: library part CMP-0120776-1, "0.1μF ±10% 630V Ceramic Capacitor X7R 1812 (4532 Metric)", Digikey Part Number=732-12117-1-ND, Manufacturer="Wurth Electronics", Mouser Part Number=710-885342211006, Operating Temperature Range="-55°C to +125°C", TempCo=15%, Temperature Characteristic=X7R, Tolerance_%=10%, ValueDisplayed=100nF
D1 D3: library part CMP-0121865-2, "Diode 600 V 30A Through Hole TO-247-2", Digikey Part Number=1740-1258-ND, Forward Current=30A, Manufacturer="WeEn Semiconductors", Max Surge Forward Current=270A, Mouser Part Number=771-BYC30W-600PQ, Operating Temperature Range="to +175°C", Part Number=BYC30W-600PQ_HOR, Peak Reverse Current=10uA
D2: "Diode, Switching-Bridge, 600 V, 3 A, TH", Manufacturer=Vishay-Semiconductor, Supplier Part Number 1=1N5406-E3/54GICT-ND, Value1=3A, Value2=1.2V
D4 D8 D10: library part CMP-0028457-2, "Diode, Schottky, 30 V, 0.2 A, SOD-123", Manufacturer="ON Semiconductor", Value1=0.2A, Value2=0.8V
D5: library part CMP-0079921-3, "LED, Green, SMD", Color=Green, Manufacturer=Lite-On, Value1=W, Value2=2V
D6 D7: "Diode, P-N, 1000 V, 1 A, 3.9x1.7x1.8mm", Manufacturer="Comchip Technology", Supplier Part Number 1=641-1330-1-ND, Value1=1A, Value2=1.1V
D9 D14: library part CMP-0005835-4, "Diode, Zener, 18 V, 200 mW, SOD-323", Manufacturer="Diodes Inc.", Power_W=200mW, Value1=0.2W
D11 D12: library part CMP-0029001-1, "Diode, Ultrafast, 100 V, 0.15 A, SOD-123", Manufacturer="Diodes Inc.", Supplier Part Number 1=1N4148W-FDICT-ND, Value1=0.15A, Value2=1.25V
D13 D15: library part CMP-0076882-1, "Diode, Ultrafast, 1000 V, 1 A, SMA", Manufacturer="Diodes Inc.", Supplier Part Number 1=US1M-FDICT-ND, Value1=1A, Value2=1.7V
D16: library part CMP-0079922-3, "LED, Red, SMD", Color=Red, Manufacturer=Lite-On, Value1=W, Value2=2V
F1: library part CMP-0090478-2, Digikey Part Number=F10249-ND, Fuse Current=25A, Fuse Interrupt Dc Current=10000A, Manufacturer=Littelfuse, Mouser Part Number=576-0525025.MXEP, Operating Temperature Range="-55°C to +125°C"
FID1 FID2 FID3: "Fiducial mark.  There is nothing to buy or mount.", Manufacturer=N/A
HS1: library part CMP-0122056-1, Manufacturer="Texas Instruments", Operating Temperature Range=to
K1: library part CMP-0121970-1, "Electromechanical Relay 12VDC 144Ohm 30A SPST-NO (32.51x27.43x20.4)mm THT Industrial Relay", Coil Power_W=1W, Coil Resistance=144Ω, Coil Voltage_VDC=12V, Contact Rating_A=30A, Digikey Part Number=PB302-ND, Manufacturer=TE, Mouser Part Number=655-T9AS1D12-12, Operating Temperature Range=to
L1: library part CMP-0121837-1, "PFC Inductor", Manufacturer="Qingdao Yunlu", Operating Temperature Range="-25°C to +130°C", Test Frequency=50kHz
L2 L3: library part CMP-0121838-1, "Common mode inductor", Manufacturer="Qingdao Yunlu", Operating Temperature Range="-25°C to +130°C", Test Frequency=100kHz
L5: library part CMP-0064862-2, "Inductor, Shielded Drum Core, Metal Composite, 1.8 mH, 0.35 A, 2.7 ohm, TH", Manufacturer="Wurth Elektronik", Supplier Part Number 1=732-3264-ND, Value1="2.7 ohm", Value2=0.35A, ValueDisplayed=1.8mH
LOGO1 LOGO3: library part CMP-0074837-1, "IEC 61010-1 Hot Surface Warning"
LOGO4 ?: library part CMP-0074835-1, "IEC 61010-1 High Voltage Warning"
Logo5: library part CMP-0074844-1
Logo6: library part CMP-0074838-1, "Texas Instrument Corporate Signature"
MP1 MP2 MP3 MP4 MP5 MP6: library part CMP-0087151-1, Manufacturer="Wurth Electronics"
P1 P2 P3 P4 P5: library part CMP-0089624-1, Current_A=20A, Digikey Part Number=A29938CT-ND, Manufacturer="TE Connectivity", Mouser Part Number=571-638241, Operating Temperature Range="-40°C to +105°C"
Q1 Q6: library part CMP-0121869-2, "Trans MOSFET N-CH 600V 31A 3-Pin(3+Tab) TO-247 Tube", Digikey Part Number=448-IPW60R099CPFKSA1-ND, Drain To Source Breakdown Voltage=600V, Input Capacitace At Vds="2800pF @ 100V", Manufacturer="Infineon Technologies", Mouser Part Number=726-IPW60R099CPFKSA1, Operating Temperature Range="-55°C to +150°C", Part Number=IPW60R099CPFKSA1_HOR, Power_W=255W, Pulse Drain Current=93A, Typ Forward Diode Voltage=0.9V
Q2: library part CMP-0000326-2, "Transistor, PNP, 40 V, 0.2 A, SOT-23", Manufacturer="Diodes Inc.", Supplier Part Number 1=MMBT3906-FDICT-ND, Value1="0.2 A", Value2=400
Q3: library part CMP-0000777-1, "MOSFET, N-CH, 60 V, 0.32 A, AEC-Q101, SOT-23", Alternate Manufacturer=None, Manufacturer="ON Semiconductor", Supplier Part Number 1=2V7002KT1GOSCT-ND, Value1=2, Value2="0.7 nC"
Q4: library part CMP-0000387-2, "Transistor, NPN, 40 V, 0.2 A, SOT-23", Manufacturer="Diodes Inc.", Supplier Part Number 1=MMBT3904-FDICT-ND, Value1="0.2 A", Value2=400
R1 R10 R13 R15 R19 R23 R31 R42 R47: library part CMP-0022746-5, "RES, 10.0 k, 1%, 0.1 W, 0603", Manufacturer=Yageo, Power_W=100mW, Supplier Part Number 1=311-10.0KHRCT-ND, TempCo="100 ppm/C", Tolerance_%=1%, Value2=0.1W, Value_Code=10k0, ValueDisplayed=10.0k
R2: library part CMP-0096746-1, "0 Ohms Jumper 1W Chip Resistor 2512 (6432 Metric) Moisture Resistant Thick Film", Digikey Part Number=13-RC2512FK-070RLCT-ND, Manufacturer=YAGEO, Max Current=10A, Mouser Part Number=603-RC2512FK-070RL, Operating Temperature Range="-55°C to +155°C", Power_W=1W
R3 R28 R33 R40: library part CMP-0018087-2, "RES, 22.0, 1%, 0.25 W, 1206", Manufacturer="Yageo America", Power_W=250mW, Supplier Part Number 1=311-22.0FRCT-ND, TempCo="100 ppm/C", Tolerance_%=1%, Value2=0.25W, Value_Code=22R0, ValueDisplayed=22.0
R4 R5 R45: library part CMP-0015807-2, "RES, 0.01, 1%, 1 W, 2512", Manufacturer=Panasonic, Power_W=1W, Supplier Part Number 1=P10MCT-ND, TempCo="100 ppm/C", Tolerance_%=1%, Value_Code=R010, ValueDisplayed=0.01
R6 R7 R8 R20 R21 R22 R25 R26 R27: library part CMP-0018207-2, "RES, 332 k, 1%, 0.25 W, 1206", Manufacturer="Yageo America", Power_W=250mW, Supplier Part Number 1=311-332KFRCT-ND, TempCo="100 ppm/C", Tolerance_%=1%, Value2=0.25W, Value_Code=332k
R9: library part CMP-0022852-5, "RES, 18.0 k, 1%, 0.1 W, 0603", Manufacturer=Yageo, Power_W=100mW, Supplier Part Number 1=311-18.0KHRCT-ND, TempCo="100 ppm/C", Tolerance_%=1%, Value2=0.1W, Value_Code=18k0, ValueDisplayed=18.0k
R11: library part CMP-0022918-5, "RES, 220, 1%, 0.1 W, 0603", Manufacturer=Yageo, Power_W=100mW, Supplier Part Number 1=311-220HRCT-ND, TempCo="100 ppm/C", Tolerance_%=1%, Value2=0.1W, Value_Code=220R, ValueDisplayed=220
R12 R17 R38: library part CMP-0023133-5, "RES, 47.0 k, 1%, 0.1 W, 0603", Manufacturer=Yageo, Power_W=100mW, Supplier Part Number 1=311-47.0KHRCT-ND, TempCo="100 ppm/C", Tolerance_%=1%, Value2=0.1W, Value_Code=47k0, ValueDisplayed=47.0k
R14: library part CMP-0022828-5, "RES, 16.2 k, 1%, 0.1 W, 0603", Manufacturer=Yageo, Power_W=100mW, Supplier Part Number 1=311-16.2KHRCT-ND, TempCo="100 ppm/C", Tolerance_%=1%, Value2=0.1W, Value_Code=16k2, ValueDisplayed=16.2k
R16: library part CMP-0022895-5, "RES, 1.00 k, 1%, 0.1 W, 0603", Manufacturer=Yageo, Power_W=100mW, Supplier Part Number 1=311-1.00KHRCT-ND, TempCo="100 ppm/C", Tolerance_%=1%, Value2=0.1W, Value_Code=1k00, ValueDisplayed=1.00k
R18: library part CMP-0018059-2, "RES, 1.00, 1%, 0.25 W, 1206", Manufacturer="Yageo America", Power_W=250mW, Supplier Part Number 1=311-1.00FRCT-ND, TempCo="200 ppm/C", Tolerance_%=1%, Value2=0.25W, Value_Code=1R00, ValueDisplayed=1.00
R24 R41: library part CMP-0018350-2, "RES, 4.70, 1%, 0.25 W, 1206", Manufacturer="Yageo America", Power_W=250mW, Supplier Part Number 1=311-4.70FRCT-ND, TempCo="200 ppm/C", Tolerance_%=1%, Value2=0.25W, Value_Code=4R70, ValueDisplayed=4.70
R29 R30 R32 R34 R35 R36: library part CMP-0017836-2, "RES, 100 k, 1%, 0.25 W, 1206", Manufacturer="Yageo America", Power_W=250mW, Supplier Part Number 1=311-100KFRCT-ND, TempCo="100 ppm/C", Tolerance_%=1%, Value2=0.25W, Value_Code=100k
R43: "RES, 100, 0.5%, 0.1 W, 0603", Manufacturer="Yageo America", Power_W=0.1, TempCo="50 ppm/C", Tolerance_%=0.5, Value1=0.5%, Value2=0.1W, Value_Code=100R, ValueDisplayed=100
R44 R50: library part CMP-0025885-5, "RES, 0, 5%, 0.1 W, 0603", Manufacturer=Yageo, Power_W=100mW, Supplier Part Number 1=311-0.0GRCT-ND, TempCo="200 ppm/C", Tolerance_%=5%, Value2=0.1W, Value_Code=0000, ValueDisplayed=0
R46: library part CMP-0022786-4, "RES, 133 k, 1%, 0.1 W, 0603", Manufacturer=Yageo, Power_W=100mW, Supplier Part Number 1=311-133KHRCT-ND, TempCo="100 ppm/C", Tolerance_%=1%, Value2=0.1W, Value_Code=133k
R48: library part CMP-0022914-5, "RES, 21.0 k, 1%, 0.1 W, 0603", Manufacturer=Yageo, Power_W=100mW, Supplier Part Number 1=311-21.0KHRCT-ND, TempCo="100 ppm/C", Tolerance_%=1%, Value2=0.1W, Value_Code=21k0, ValueDisplayed=21.0k
RT1: library part CMP-0123150-1, "Ceramic PTC Thermistor", Manufacturer="Thinking Electronic", Operating Temperature Range="-20°C to +85°C", Tolerance_%=30%
RV1: library part CMP-0001785-2, "VARISTOR 558V 4.5KA, TH", Manufacturer=WURTH, PartNumber=820543011, Supplier Part Number 1=732-13277-1-ND
S1: library part CMP-0122038-1, "Toggle Sw, SPDT, 1A, 30VDC, Panel/th Rohs Compliant: Yes", Coil Resistance_ohm=30mΩ, Contact Current Rating=1A, Digikey Part Number=732-472123010111-ND, Manufacturer="Wurth Electronics", Mouser Part Number=710-472123010111, Operating Temperature Range="-40°C to +85°C"
TP1 TP2 TP3 TP4 TP5 TP7 TP8 TP9: "Test Point, Miniature, Red, TH", Manufacturer=Keystone, Supplier Part Number 1=5000K-ND
TP6: "Test Point, Miniature, Black, TH", Manufacturer=Keystone, Supplier Part Number 1=5001K-ND
TP10 TP11 TP12: library part CMP-0055138-2, "Test Point, Miniature, Black, TH", Color=Black, Manufacturer="Keystone Electronics", Supplier Part Number 1=36-5001-ND
U1: "8-PIN CONTINUOUS CONDUCTION MODE (CCM) PFC CONTROLLER, D0008A", Alternate Manufacturer=None, Manufacturer="Texas Instruments", Supplier Part Number 1=296-37132-5-ND
U2: library part CMP-0073916-1, "Dual, 5A, High-Speed Low-Side Power MOSFET Driver, D0008A (SOIC-8)", Alternate Manufacturer="Texas Instruments", Alternate PartNumber=UCC27524D
U3: library part CMP-0074092-1, "700-V Lowest Quiescent Current Off-Line Switcher, D0007A (SOIC-7)", Alternate Manufacturer="Texas Instruments", Alternate PartNumber=UCC28881D

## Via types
v1: diameter 1, hole 0.6, Top Layer to Bottom Layer, 423 vias
v2: diameter 1.27, hole 0.711, Top Layer to Bottom Layer, 82 vias
v3: diameter 0.6, hole 0.2, Top Layer to Bottom Layer, 38 vias
v4: diameter 0.864, hole 0.406, Top Layer to Bottom Layer, 2 vias

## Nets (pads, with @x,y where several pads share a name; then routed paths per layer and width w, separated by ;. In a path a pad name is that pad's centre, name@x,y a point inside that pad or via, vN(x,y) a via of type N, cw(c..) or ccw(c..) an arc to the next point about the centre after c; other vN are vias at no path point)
15V: C12.1 C16.1 C19.1 C28.2 R13.1 R18.2 R33.1 TP9.1 U1.7 U2.6 | length 264.3
  Top Layer w0.5: C12.1@58.75,81.7 58.914,81.864 60.136,81.864 C16.1@60.2,81.8 60.4,82 63.2,82 ; C12.1@58.85,81.5 58.85,79.15 59.146,78.854 60.681,78.854 U1.7@60.7,78.835 ; TP9.1@63.281,84.906 63.234,84.859 63.234,82.034 63.2,82 ; U2.6@83.035,80.225 83.035,78.165 83.2,78 ; C28.2@86.1,78.675 86.114,78.689 87.725,78.689 R13.1@87.736,78.677 87.759,78.7 91.71,78.7 93.7,80.69 93.7,81.4 99.5,87.2 99.5,90.2 109.9,100.6 109.9,120.5 112.2,122.8 115.299,122.8 115.592,123.093 115.592,124.792 116.15,125.35 116.15,126.6 R18.2@116.35,126.8 ; C28.2@86.1,78.7 84.427,78.7 83.727,78 83.2,78 ; 63.2,82 67.361,82 71.361,78 83.2,78
  Top Layer w0.8: v3(113,135.2) 113,136.7 118.6,142.3 122.706,142.3 123.786,141.22 187.28,141.22 196.6,131.9 196.6,79.325 193.15,75.875 R33.1@193.15,75.6 ; v3(114.4,132.8) 114.4,131.526 114.6,131.326 C19.1@114.6,129.7 ; C19.1@114.85,129.7 114.85,129.425 116.3,127.975 116.3,126.85 R18.2@116.35,126.8
  Bottom Layer w0.8: v3(113,135.2) 113,133.5 113.7,132.8 v3(114.4,132.8)
ACSENSE: C20.1 Q4.1 R22.1 R23.2 | length 9.5
  Top Layer w0.5: C20.1@81.45,69.5 81.779,69.171 81.779,68.193 82.071,67.9 82.775,67.9 83.25,67.425 R23.2@83.25,67.025 ; R22.1@82.45,63.544 82.85,63.944 82.85,65.15 83.5,65.8 R23.2@83.5,66.8 83.507,66.807 84.457,66.807 84.95,67.3 84.95,67.5 85,67.55 Q4.1@85.2,67.55
BIAS: D14.1 Q2.2 R15.1 R31.2 R50.2 | length 16.9
  Top Layer w0.5: R15.1@115.5,132.25 115.55,132.2 117.05,132.2 117.1,132.15 117.975,133.025 117.975,133.275 118.8,134.1 120.5,134.1 122.223,135.823 R50.2@127.064,135.823 127.064,137.495 D14.1@126.959,137.6 126.2,137.6 125.961,137.361 125.548,137.361 R31.2@125.323,137.136
GNDE: C6.1 C7.1 C8.1 C9.1 C23.1 C26.1 P3.1 | length 226.7
  Top Layer w1: C9.1@165.14,32.207 C9.1@165.207,32.274
  Bottom Layer w1.3: C9.1@165.207,32.274 165.207,29.106 165.3,29.014 C8.1@165.3,29
  Bottom Layer w1.5: C23.1@31.5,26.1 33.6,28.2 ; C26.1@31.5,29.5 32.8,28.2 33.6,28.2 ; C6.1@99.1,26.8 97.7,28.2 97.1,28.2 ; 164.8,29.5 122.4,29.5 ; P3.1@179.46,3.2 179.284,3.2 177.884,1.8 126.7,1.8 122.4,6.1 122.4,29.5 ; 33.6,28.2 97.1,28.2 ; 97.1,28.2 C7.1@99.1,30.2 99.8,29.5 122.4,29.5
  other v1: 179.5,1.743 184.58,1.743 178.2,2.4 180.675,2.418 183.33,2.418 185.755,2.418 178.15,3.893 180.75,3.893 183.23,3.893 185.83,3.893 179.425,4.643 184.505,4.643
InrushDelay: C25.1 D9.1 R27.2 R38.1 | length 82.7
  Top Layer w0.5: R38.1@72.3,74.3 75.5,74.3 78.293,71.507 82.593,71.507 v3(82.6,71.5) ; v3(84.331,72.805) 84.826,73.3 86,73.3 C25.1@86.3,73.6 87.9,73.6 88.8,74.5 88.8,75.925 90.225,77.35 R27.2@90.5,77.35 90.9,77.75 92.025,77.75 96.65,82.375 96.65,83.36 100.3,87.01 100.3,90 110.7,100.4 110.7,120 112.8,122.1 115.842,122.1 116.667,122.925 D9.1@116.667,124.125
  Bottom Layer w0.5: v3(82.6,71.5) 82.619,71.519 83.045,71.519 v3(84.331,72.805)
NetBR1_1: BR1.1 R2.1
  other v1: 24.04,74.043 22.79,74.718 25.215,74.718 22.69,76.193 25.29,76.193 23.965,76.943
  other v2: 21.9,77.7 23.6,78.9 19.9,79.9 23.6,80.5 19.9,81.5 23.6,82
NetBR1_2: BR1.2 C22.1 C26.2 D6.2 L2.2 R32.1 | length 2.3
  Top Layer w1: v1(25.215,64.718) 25.233,64.7 D6.2@27.55,64.7
  other v1: 41,34.7 42.1,34.8 40,34.9 43.2,35.3 39.1,35.4 38.3,36.1 43.9,36.1 37.8,37.2 44.4,37.2 37.6,38.3 44.53,38.354 37.8,39.4 44.38,39.404 38.3,40.3 43.9,40.3 43.1,41 39,41.1 42.2,41.5 40.1,41.6 41.2,41.7 24.04,64.043 22.79,64.718 22.69,66.193 25.29,66.193 23.965,66.943
  other v2: 22.9,34.85 19,35.2 22.9,38.6 19.2,41.625 22.9,42.475 3.175,68 5.05,68 7.05,68 8.925,68 10.8,68
NetBR1_3: BR1.3 C22.2 C23.2 D7.2 L2.3 R29.2 | length 17.5
  Top Layer w1: R29.2@6.5,14.4 12.155,14.4 13.305,15.55 C22.2@19,15.55 ; BR1.3@24,58 24.23,58.23 26.13,58.23 27.55,59.65 D7.2@27.55,59.9
  other v1: 41,16.7 42.1,16.8 40,16.9 43.2,17.3 39.1,17.4 38.3,18.1 43.9,18.1 37.8,19.2 44.4,19.2 37.6,20.3 44.53,20.354 37.8,21.4 44.38,21.404 38.3,22.3 43.9,22.3 43.1,23 39,23.1 42.2,23.5 40.1,23.6 41.2,23.7 24.04,56.543 22.79,57.218 25.215,57.218 22.69,58.693 25.5,58.7 23.965,59.443
  other v2: 16.2,5.6 16.2,7.475 16.2,9.35 16.2,11.35 16.2,13.225 16.2,16.975 16.2,18.85 18.9,20.45 21,20.525 23.2,20.6
NetC1_2: C1.2 C8.2 F1.2 L3.4 RV1.2 | length 3.3
  Top Layer w1: 173.05,22.85 RV1.2@173.05,26.1
  other v1: 151.171,12.301 149.921,12.976 152.346,12.976 149.821,14.451 152.421,14.451 151.096,15.201 141.6,17.1 142.7,17.2 140.6,17.3 143.8,17.7 139.7,17.8 138.9,18.5 144.5,18.5 138.4,19.6 145,19.6 138.2,20.7 145.13,20.754 138.4,21.8 144.98,21.804 138.9,22.7 144.5,22.7 143.7,23.4 139.6,23.5 142.8,23.9 140.7,24 141.8,24.1
NetC2_1: C2.1 C7.2 L2.1 L3.2
  other v1: 75,34.7 76.1,34.8 74,34.9 107.6,35.1 108.7,35.2 77.2,35.3 106.6,35.3 73.1,35.4 109.8,35.7 105.7,35.8 72.3,36.1 77.9,36.1 104.9,36.5 110.5,36.5 71.8,37.2 78.4,37.2 104.4,37.6 111,37.6 71.6,38.3 71.6,38.3 78.53,38.354 104.2,38.7 104.2,38.7 111.13,38.754 71.8,39.4 78.38,39.404 104.4,39.8 110.98,39.804 72.3,40.3 77.9,40.3 104.9,40.7 110.5,40.7 77.1,41 73,41.1 109.7,41.4 76.2,41.5 105.6,41.5 74.1,41.6 75.2,41.7 108.8,41.9 106.7,42 107.8,42.1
